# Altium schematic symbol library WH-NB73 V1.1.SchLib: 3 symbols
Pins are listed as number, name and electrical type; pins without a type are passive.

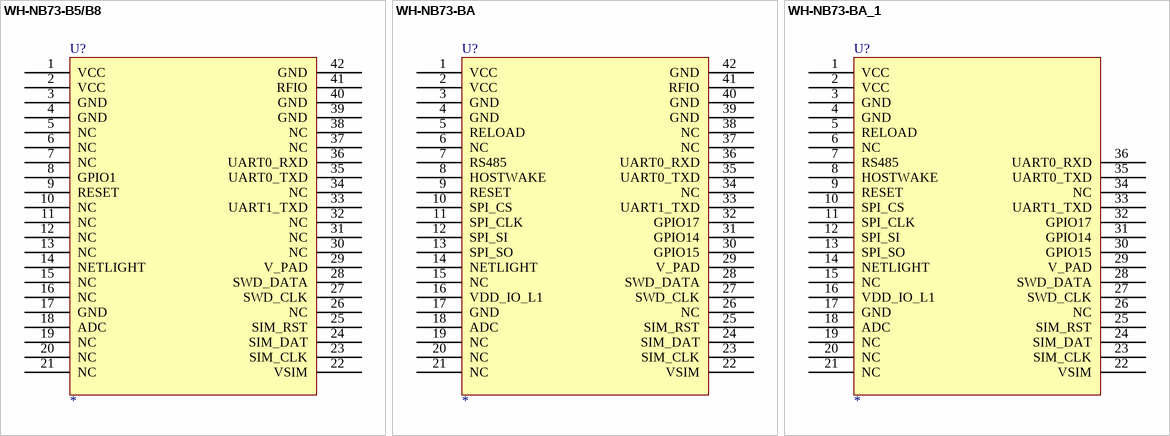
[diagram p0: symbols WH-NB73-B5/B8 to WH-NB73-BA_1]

## WH-NB73-B5/B8
designator U?
pins: 1 VCC, 2 VCC, 3 GND, 4 GND, 5 NC, 6 NC, 7 NC, 8 GPIO1, 9 RESET, 10 NC, 11 NC, 12 NC, 13 NC, 14 NETLIGHT, 15 NC, 16 NC, 17 GND, 18 ADC, 19 NC, 20 NC, 21 NC, 22 VSIM, 23 SIM_CLK, 24 SIM_DAT, 25 SIM_RST, 26 NC, 27 SWD_CLK, 28 SWD_DATA, 29 V_PAD, 30 NC, 31 NC, 32 NC, 33 UART1_TXD, 34 NC, 35 UART0_TXD, 36 UART0_RXD, 37 NC, 38 NC, 39 GND, 40 GND, 41 RFIO, 42 GND
2 alternate drawings of the same symbol

## WH-NB73-BA
designator U?
EXTERNAL ANTENNA
pins: 1 VCC, 2 VCC, 3 GND, 4 GND, 5 RELOAD, 6 NC, 7 RS485, 8 HOSTWAKE, 9 RESET, 10 SPI_CS, 11 SPI_CLK, 12 SPI_SI, 13 SPI_SO, 14 NETLIGHT, 15 NC, 16 VDD_IO_L1, 17 GND, 18 ADC, 19 NC, 20 NC, 21 NC, 22 VSIM, 23 SIM_CLK, 24 SIM_DAT, 25 SIM_RST, 26 NC, 27 SWD_CLK, 28 SWD_DATA, 29 V_PAD, 30 GPIO15, 31 GPIO14, 32 GPIO17, 33 UART1_TXD, 34 NC, 35 UART0_TXD, 36 UART0_RXD, 37 NC, 38 NC, 39 GND, 40 GND, 41 RFIO, 42 GND
2 alternate drawings of the same symbol

## WH-NB73-BA_1
designator U?
INTERNAL ANTENNA
pins: 1 VCC, 2 VCC, 3 GND, 4 GND, 5 RELOAD, 6 NC, 7 RS485, 8 HOSTWAKE, 9 RESET, 10 SPI_CS, 11 SPI_CLK, 12 SPI_SI, 13 SPI_SO, 14 NETLIGHT, 15 NC, 16 VDD_IO_L1, 17 GND, 18 ADC, 19 NC, 20 NC, 21 NC, 22 VSIM, 23 SIM_CLK, 24 SIM_DAT, 25 SIM_RST, 26 NC, 27 SWD_CLK, 28 SWD_DATA, 29 V_PAD, 30 GPIO15, 31 GPIO14, 32 GPIO17, 33 UART1_TXD, 34 NC, 35 UART0_TXD, 36 UART0_RXD
2 alternate drawings of the same symbol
